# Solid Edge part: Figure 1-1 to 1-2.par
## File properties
Author: CADCIM
Template: normal.par
Last saved by: Rajat Kamboj
Revision: 21
Application: Solid Edge
Accuracy: 0.99
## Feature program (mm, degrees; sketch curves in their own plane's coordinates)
sketch for "unnamed Protrusion 1" plane through (0, 0, 0) normal (0, 0, 1) x-axis (1, 0, 0)
  line (-63.0032, 49) -> (-56, -71)
  line (-56, -71) -> (56, -71)
  line (56, -71) -> (63.0032, 49)
  line (63.0032, 49) -> (0, 54)
  line (0, 54) -> (-63.0032, 49)
  dimension (linear) = 56
  dimension (linear) = 56
extrude "unnamed Protrusion 1" add finite 4 along +normal
fillet "Round_1" radius 15
sketch for "ExtrudedProtrusion_3" plane through (0, -8.5, 0) normal (0, 0, -1) x-axis (-1, 0, 0)
extrude "ExtrudedProtrusion_3" add finite 12 along -normal
pattern "unnamed Pattern 1" of "ExtrudedProtrusion_3"
pattern "unnamed Pattern 2"
sketch for "unnamed Protrusion 2" plane through (-1.0316, 2.3101, 4) normal (0, 0, 1) x-axis (-1, 0, 0)
extrude "unnamed Protrusion 2" add finite 5 along +normal
sketch for "Hole_22" plane through (40.9331, -54.9887, 12) normal (0, 0, 1) x-axis (1, 0, 0)
  hole centre (-0.4331, -0.0113) bore radius 4.5
hole "Hole_22" diameter 9 through  CounterBoreDepth = 5 mm
pattern "unnamed Pattern 3" of "Hole_22"
hole "unnamed Hole 1" through
hole "unnamed Hole 2" through
hole "unnamed Hole 3" through
sketch for "Hole_29" plane through (-1.0316, -6.1899, 9) normal (0, 0, 1) x-axis (1, 0, 0)
  hole centre (0, 0) bore radius 11
hole "Hole_29" diameter 22 through
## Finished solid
Body 1: solid body, 34 faces, 55 edges, 18 vertices.
  Faces by surface: cylinder 18, plane 16
  Edges by curve: circle 36, line 19
Bounding box of the edges (mm): 124.346 x 125.000 x 12.000, from (-62.1729, -71, 0) to (62.1729, 54, 12).
Cylindrical faces by radius (mm): R4.5 x4, R7.5 x4, R10.7006 x4, R11 x1, R15 x4, R20 x1
Planar faces by outward normal: +z 10, -y 1, -z 1, oblique 4
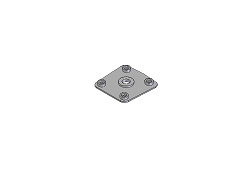
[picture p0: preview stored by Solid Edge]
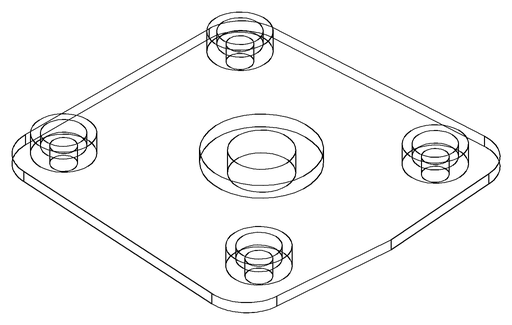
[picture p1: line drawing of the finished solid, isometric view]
